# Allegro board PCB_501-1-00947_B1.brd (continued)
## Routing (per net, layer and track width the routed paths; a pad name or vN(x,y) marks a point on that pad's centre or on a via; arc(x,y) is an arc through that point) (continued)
ENET_RST_B: length 119.4
  TOP w0.102: U7.R2 67.89,80.97 68.32,80.54 68.32,80.34 69.49,79.17
  TOP w0.127: v1(57.75,30.35) 63.21,30.35 v1(63.97,31.11) ; v1(70.86,78.77) 70.83,78.77 70.43,79.17 69.49,79.17 ; v1(30.71,34.12) 30.71,34.17 30.83,34.29 U13.43
  BOTTOM w0.127: v1(57.75,30.35) 54.7,27.3 41.88,27.3 40.02,25.44 28.25,25.44 27.39,26.3 27.39,30.4 27.91,30.91 27.91,32.97 26.93,33.95 26.93,34.46 27.84,35.37 28.92,35.37 30.04,34.25 R131.2 30.63,34.12 v1(30.71,34.12) ; v1(63.97,31.11) 72.01,31.11 76.23,35.33 76.23,65.89 74.9,67.22 74.9,74.07 70.86,78.11 v1(70.86,78.77)
ESPI3_MISO: length 79.2
  TOP w0.102: U7.D9 v2(58.34,78.87)
  L3_INT_1 w0.102: 57.59,76.93 57.59,77.6 58.34,78.35 v2(58.34,78.87)
  L3_INT_1 w0.127: v1(53.89,69.6) 54.66,70.37 54.66,73.67 54.9,73.91 54.9,74.24 57.59,76.93
  L6_INT_2 w0.127: v1(16.47,49.58) 17.54,50.65 17.58,50.65 17.76,50.83 45.94,50.83 v1(54.58,59.46)
  BOTTOM w0.137: v1(53.89,69.6) 53.89,60.73 54.58,60.04 v1(54.58,59.46) ; R358.2 13.35,39.8 14.07,40.52 14.07,43.82 13.21,44.68 13.21,46.32 v1(16.47,49.58) 17.33,50.44 U23.12
ESPI3_MOSI: length 78.3
  TOP w0.102: U7.D8 58.87,78.34 v2(58.87,78.34)
  L3_INT_1 w0.102: v2(58.87,78.34) 58.74,78.21 58.74,77.69
  L3_INT_1 w0.127: 58.74,77.69 58.74,77.34 57.19,75.79 57.19,73.4 55.75,71.96 55.75,69.78 v1(54.73,68.76)
  L6_INT_2 w0.127: v1(55.11,59.05) 46.55,50.5 29.03,50.5 28.47,49.94 25.17,49.94 25.17,49.94 24.8,49.94 24.79,49.94 18.11,49.94 v1(17.8,50.24)
  BOTTOM w0.137: R357.2 12.93,38.95 14.42,40.44 14.42,46.86 v1(17.8,50.24) 18.63,51.07 U23.14 ; v1(54.73,68.76) 55.11,68.38 v1(55.11,59.05)
ESPI3_SCLK: length 79.3
  TOP w0.102: U7.E9 v2(58.87,79.4)
  L3_INT_1 w0.102: v2(58.87,79.4) 58.34,79.4 56.75,77.81 56.75,77.08 55.65,75.97
  L3_INT_1 w0.127: v1(53.09,69.85) 53.15,69.85 53.69,70.38 53.69,74.02 55.65,75.97
  L6_INT_2 w0.127: v1(54.07,59.87) 45.45,51.25 21.26,51.25 v1(20.95,51.55)
  BOTTOM w0.137: v1(54.07,59.87) 53.12,60.82 53.12,69.68 53.09,69.7 v1(53.09,69.85) ; R356.2 13.98,37.89 14.93,38.84 14.93,46.75 17.18,49 18.13,49 19.93,50.8 U23.16 20.53,51.92 20.91,51.55 v1(20.95,51.55)
FB_HPOUTL: length 7.5
  TOP w0.254: FB11.2 112.1,38.11 D23.2 114.16,38.15 R367.2 118.24,38.51 J15.2
FB_HPOUTR: length 17
  TOP w0.254: J15.3 121.19,31.1 115.5,36.79 112.2,36.79 D24.2 112.02,36.76 111.98,36.71 FB12.2
FB_VDD_SD: length 16.5
  L3_INT_1 w0.508: v1(94.07,52.2) 94.42,51.85 104.88,51.85 v1(106.47,53.43)
  BOTTOM w0.508: R102.2 95.72,53.23 Q6.3 v1(94.07,52.2) ; FB42.1 v1(106.47,53.43)
FT_RSTOUT_B: length 6.7
  BOTTOM w0.127: U18.5 103.98,121.14 104.3,121.46 105.35,121.46 105.9,120.91 R159.2
FT_RX1: length 1.9
  BOTTOM w0.137: U18.23 111.06,110.63 U17.3
FT_RX2: length 9.9
  BOTTOM w0.137: U19.3 102.6,103.48 100.85,105.23 100.85,109.34 101.29,109.77 101.29,110.87 101.02,111.13 U18.39
FT_TX1: length 1.9
  BOTTOM w0.137: U18.24 111.06,110.13 U17.2
FT_TX2: length 10.7
  BOTTOM w0.137: U18.40 101.21,111.63 101.71,111.13 101.71,109.52 101.32,109.13 101.32,105.32 103.1,103.54 U19.2
FUSE_FSOURCE: length 2.8
  TOP w0.254: v2(65.85,86.54) 65.86,86.54 66.1,86.3 U7.V8
  BOTTOM w0.254: C93.1 66.21,86.18 v2(65.85,86.54)
  BOTTOM w0.406: v1(78.32,81.9) 78.57,82.14 R30.1
GPANAIO: length 8.7
  TOP w0.102: v2(67.89,84.17) 67.89,84.18 U7.V4
  TOP w0.127: v1(74.36,82.5) 74.66,82.2 TP6.1
  L6_INT_2 w0.102: 69.67,83.05 69.51,83.05 68.39,84.17 v2(67.89,84.17)
  L6_INT_2 w0.127: 69.67,83.05 73.81,83.05 v1(74.36,82.5)
GPIO1: length 7.9
  TOP w0.127: U5.11 19.98,88.67 20.95,89.64 20.95,94.11 21.4,94.56 R762.1
GPIO3: length 3.3
  TOP w0.127: R752.1 12.54,89.23 12.88,88.89 12.99,88.78 13.1,88.67 U5.26
GPIO_EPDC_D4: length 6.8
  TOP w0.102: v2(56.22,91.6) U7.N22
  BOTTOM w0.127: v2(56.22,91.6) 55.57,91.6 54.58,92.58 TP10.1 54.15,92.28 53.46,92.28 53.35,92.39 53.35,92.39 52.04,93.7 52.04,94.39 C366.1
GPIO_SD3_CLK: length 4.9
  TOP w0.137: R444.2 64.29,71.37 64.29,72.03 62.53,73.79 62.53,74.15 62.06,74.62 U7.C1
GPIO_SD3_CMD: length 4.8
  TOP w0.137: R445.2 65.99,72.79 63.12,75.66 U7.E1
GPIO_SD3_DATA0: length 6.5
  TOP w0.137: R436.2 63.08,70.02 63.08,70.02 63.02,70.08 63.02,70.08 63.02,71.19 62.78,71.42 62.5,71.42 62.35,71.58 62.35,72.01 62.15,72.21 61.66,72.21 61.49,72.38 61.49,73.59 60.99,74.09 U7.B2
GPIO_SD3_DATA1: length 6.6
  TOP w0.137: 60.46,74.1 60.46,72.81 62.27,71 62.27,70.61 61.83,70.17 61.83,69.71 62.58,68.96 R437.2
GPIO_SD3_DATA2: length 6.3
  TOP w0.102: 64.46,75.98 63.65,76.79 U7.G2
  TOP w0.127: 64.46,75.98 64.74,75.69 65.93,75.69
  TOP w0.137: R439.2 68.39,74.73 67.99,75.14 66.49,75.14 65.93,75.69
GPIO_SD3_DATA3: length 6.5
  TOP w0.137: R438.2 67.64,74.45 66.78,74.45 66.28,73.95 66.05,73.95 65.82,74.17 65.82,74.37 66.18,74.73 66.18,74.89 65.81,75.26 64.61,75.26 U7.F1
GPIO_SD3_DATA4: length 5.9
  TOP w0.137: U7.F2 63.12,76.2 65.86,73.45 66.24,73.45 66.25,73.45 R440.2
GPIO_SD3_DATA5: length 5.7
  TOP w0.137: U7.E2 62.76,76.05 62.76,75.54 62.97,75.33 63.06,75.33 64.9,73.49 64.9,72.96 65.29,72.57 65.6,72.57 R441.2
GPIO_SD3_DATA6: length 6.2
  TOP w0.137: R443.2 64.88,72.02 64.88,72.03 64.87,72.03 64.19,72.71 64.19,72.99 64.34,73.13 64.34,73.33 64.05,73.61 63.85,73.61 63.7,73.46 63.45,73.46 62.83,74.07 62.83,74.37 62.04,75.16 61.52,75.16
GPIO_SD3_DATA7: length 5.5
  TOP w0.137: 61.53,74.1 U7.B1 61.8,73.82 61.8,72.81 62.02,72.59 63.01,72.59 63.67,71.94 63.67,70.72 R442.2
GPIO_SD3_RESET_B: length 5.6
  TOP w0.102: 64.67,76.26 U7.G1
  TOP w0.127: 64.67,76.26 64.86,76.07 66.09,76.07
  TOP w0.137: R446.2 68.41,75.37 68.21,75.57 66.58,75.57 66.09,76.07
GPIO_SD3_STROBE: length 5.7
  TOP w0.127: 65.24,77.37 U7.J1
  TOP w0.137: 65.24,77.37 66.7,75.91 68.1,75.91 68.2,76 R447.2
GWDOG_RST_B: length 43.5
  TOP w0.102: 70.45,78.5 70.06,78.89 69.18,78.89 68.98,78.69 68.42,78.69 67.36,79.75 U7.N1
  TOP w0.127: v1(73.07,75.18) 73.07,76.28 71.37,77.98 70.97,77.98 70.45,78.5 ; v1(100.69,87.67) 100.73,87.63 101.01,87.63 C382.1
  L3_INT_1 w0.127: v1(100.69,87.67) 94.05,87.67 80.75,74.37 76.21,74.37 75.4,75.18 v1(73.07,75.18)
HP_DETEC: length 21.8
  TOP w0.254: v1(110.99,34.01) R366.2 111.99,34 114.3,34 J15.4 ; v1(97.79,43.05) 97.79,41.56 U24.2
  BOTTOM w0.254: v1(97.79,43.05) 98.05,42.8 101.06,42.8 109.85,34.01 v1(110.99,34.01)
HP_L: length 7.4
  TOP w0.254: U24.31 99.13,40.36 105.02,40.36 105.81,39.57 C274.1
HP_R: length 8.5
  TOP w0.254: U24.29 99.06,39.3 100.09,39.3 100.09,39.29 102.67,39.29 105.81,36.15 C275.1
HPOUTL: length 2.7
  TOP w0.254: C274.2 C369.1 110.2,38.15 FB11.1
HPOUTR: length 2.8
  TOP w0.254: FB12.1 110.33,36.67 C370.1 108.83,35.57 C275.2
HSIC_DATA: length 14.3
  TOP w0.137: J4.1 47.61,68.35 47.6,68.34 47.6,71.92 55.08,79.4 U7.A12
HSIC_STROBE: length 15
  TOP w0.137: U7.B12 55.15,79.93 47.3,72.08 43.98,72.08 J3.1
I2C1_SCL: length 203.3
  TOP w0.127: U7.J2 65.26,78.34 65.65,77.95 65.65,77.41 66.72,76.34 v1(67.31,76.34)
  TOP w0.137: R234.1 89.1,125.21 90.18,124.13 95.49,124.13 102.38,117.24 102.38,113.19 101.6,112.41 101.6,92.12 94.56,85.07 93.68,85.07 93.1,84.5 88.11,84.5 85.25,81.64 85.25,71.93 82.74,69.42 82.74,69.42 81.66,68.35 77.96,68.35 71.2,75.1 71.2,75.58 70.07,76.71 68.28,76.71 67.91,76.34 v1(67.31,76.34) ; R231.1 70.66,70.06 v1(70.72,70.01) 72.58,70.01 80.51,62.08 85.62,62.08 R233.2
  L6_INT_2 w0.102: 54.4,95.32 56.25,93.47 56.25,93.17 58.72,90.7 58.72,87.32 58.49,87.09 58.49,86.65 58.69,86.44 58.69,86.15 58.49,85.95 58.49,83.48 58.9,83.07 58.9,82.59 60.45,81.04 61.17,81.04 61.36,81.23 62.91,81.23 63.5,80.64 63.79,80.64 63.97,80.82 65.39,80.82 65.57,80.64 65.97,80.64 66.15,80.82 66.45,80.82 66.85,80.42 66.85,76.8 v1(67.31,76.34)
  L6_INT_2 w0.127: 54.4,95.32 54.36,95.36 52.31,95.36 50.9,96.77 49.37,96.77 48.57,97.57 25.02,97.57 24.72,97.27 23,97.27 21.79,96.05 21.79,94.88 22.66,94.01 22.66,90.29 23.66,89.28 v1(25.06,89.28)
  BOTTOM w0.137: R232.1 22.88,86.22 22.9,86.22 23.16,86.48 23.16,86.5 23.33,86.68 23.33,87.57 25.05,89.28 v1(25.06,89.28) ; v1(70.72,70.01) 70.43,70.3 70.43,73.51 68.13,75.82 67.83,75.82 v1(67.31,76.34)
I2C1_SDA: length 205.7
  TOP w0.127: U7.K1 65.95,78.16 65.95,77.52 66.7,76.77 v1(67.78,76.77)
  TOP w0.137: R235.1 71.18,71.46 v1(71.18,70.57) 72.75,70.57 80.94,62.39 85.62,62.39 R237.2 ; v1(67.78,76.77) 68.04,77.04 70.24,77.04 71.66,75.63 71.66,75.06 78.02,68.69 81.6,68.69 82.62,69.71 82.62,69.71 84.96,72.05 84.96,81.76 88.72,85.52 94.6,85.52 101.16,92.08 101.16,112.97 101.79,113.6 101.79,117 95.6,123.19 R238.2
  L6_INT_2 w0.102: 54.76,95.68 59.23,91.22 59.23,90.02 59.93,89.32 59.93,86.29 59.04,85.39 59.04,84.02 61.14,81.92 61.53,81.92 62.01,81.43 63.71,81.43 63.99,81.16 65.43,81.16 65.63,81.35 66.95,81.35 67.16,81.15 67.16,79.31 67.78,78.7 v1(67.78,76.77)
  L6_INT_2 w0.127: 54.76,95.68 52.41,95.68 50.94,97.16 49.38,97.16 48.63,97.9 32.1,97.9 31.08,98.92 24.18,98.92 21.51,96.26 21.51,94.87 20.97,94.34 20.97,91.62 21.37,91.22 21.37,88.83 22.33,87.87 23.61,87.87 24,88.26 25.42,88.26 26.12,88.96 v1(26.12,89.28)
  BOTTOM w0.137: v1(67.78,76.77) 71.07,73.48 71.07,70.74 71.18,70.64 v1(71.18,70.57) ; R236.1 24.88,87.08 24.88,87.68 26.12,88.92 v1(26.12,89.28)
I2C2_SCL: length 126.3
  TOP w0.102: U7.K2 65.77,78.87 66.33,78.31 66.33,77.75 66.38,77.71 v1(66.38,77.71)
  TOP w0.137: R242.2 v1(116.55,48.39)
  L3_INT_1 w0.102: 68.81,76.85 68.46,77.2 66.89,77.2 v1(66.38,77.71)
  L3_INT_1 w0.127: 68.81,76.85 69.08,76.58 74.26,76.58 74.87,75.97 80.37,75.97 94.87,90.48 101.94,90.48 v1(101.95,90.47) 104.82,90.47 110.32,95.97 122.98,95.97 124.71,94.25 124.71,56.54 v1(116.55,48.39)
  BOTTOM w0.137: R506.2 102.58,89.83 v1(101.95,90.47) ; v1(66.38,77.71) 66.38,76.97 66.75,76.6 R61.1
I2C2_SDA: length 129.9
  TOP w0.102: U7.K3 v2(64.71,78.87)
  TOP w0.137: R247.2 v1(116.55,45.72)
  L3_INT_1 w0.102: 67.08,76.02 66.27,76.83 66.27,77.21 64.71,78.77 v2(64.71,78.87)
  L3_INT_1 w0.127: 67.08,76.02 67.16,75.94 69.05,75.94 69.41,76.3 74.15,76.3 74.75,75.7 80.54,75.7 94.75,89.9 101.13,89.9 v1(101.19,89.96) 104.7,89.96 110.44,95.69 122.01,95.69 124.36,93.34 124.36,56.89 115.97,48.5 115.97,46.3 v1(116.55,45.72)
  BOTTOM w0.102: R62.1 65.99,77.58 v2(64.71,78.87)
  BOTTOM w0.137: v1(101.19,89.96) 101.44,89.7 R504.2
I2C3_SCL: length 107.9
  TOP w0.127: U7.K5 63.65,79.93 v2(63.65,79.93)
  TOP w0.137: v1(19.4,61.21) 19.4,61.24 R723.2
  L6_INT_2 w0.127: v1(19.4,61.21) 21.04,59.56 21.04,56.3 17.73,52.98 15.98,52.98 14.4,52.98 14.36,52.98 11.64,50.26 11.64,47.13 v1(12.29,46.48) 14.34,46.48 14.69,46.12 18.25,46.12 21.41,49.28 29.03,49.28 29.63,49.88 49.74,49.88 v1(57.27,57.4)
  BOTTOM w0.102: 64.41,75.91 64.41,76.4 63.8,77.01 63.8,77.4 64.03,77.63 64.03,77.95 63.27,78.71 63.27,79 63.65,79.38 v2(63.65,79.93)
  BOTTOM w0.127: R63.1 64.41,74.72 64.41,75.91
  BOTTOM w0.137: R63.1 64.69,74.43 64.69,73.4 66,72.08 66,66.14 v1(57.27,57.4) ; R508.2 13.48,41.51 13.48,43.26 12.29,44.44 v1(12.29,46.48) ; v1(19.4,61.21) R726.2
I2C3_SDA: length 110.3
  TOP w0.127: U7.K6 63.12,80.46 v2(63.12,80.46)
  TOP w0.137: v1(20.45,61.47) 20.31,61.47 R724.2
  L6_INT_2 w0.127: v1(55.95,58.17) 47.95,50.16 29.52,50.16 28.91,49.56 21.29,49.56 18.17,46.44 15.31,46.44 14.41,47.34 v1(12.34,47.34) 11.92,47.75 11.92,50.11 14.52,52.7 15.98,52.7 17.84,52.7 21.41,56.27 21.41,60.51 v1(20.45,61.47)
  BOTTOM w0.102: v2(63.12,80.46) 63.12,79.16 62.98,79.01 62.98,78.74 62.74,78.51 62.74,78.2 63.52,77.42 63.52,76.93 64.05,76.41
  BOTTOM w0.127: 64.05,76.41 64.05,74.11 63.4,73.47 R64.1
  BOTTOM w0.137: v1(12.34,47.34) 11.72,46.72 11.72,44.51 12.93,43.3 R509.2 ; R725.2 18.25,60.86 18.38,60.73 19.71,60.73 v1(20.45,61.47) ; 63.4,73.47 65.67,71.19 65.67,66.28 63.28,63.89 63.28,63.89 58.6,59.21 58.59,59.21 57.55,58.17 v1(55.95,58.17)
I2C4_SCL: length 434.2
  TOP w0.102: U7.C12 v2(56.22,79.93)
  TOP w0.137: v1(19.94,56.92) 20,56.98 20.06,56.98 20.87,57.78 R516.2
  L3_INT_1 w0.127: v1(12.67,53.32) 12.67,51.61 13.22,51.06 13.22,46.78 12.74,46.3 12.74,46.3 12.62,46.18 12.62,45.53 10.64,43.56 10.21,43.56 8.35,41.7 8.35,34.67 5.5,31.83 5.5,18.24 7.22,16.52 12.52,16.52 12.86,16.86 14.26,16.86 21.42,24.02 47.09,24.02 49.2,26.13 49.2,66.12 50.01,66.94 50.01,74.46 51.56,76.01 51.56,76.38 53,77.81 53,78.56 53.23,78.79 v2(53.23,78.81) 53.25,78.81 53.36,78.92 55.21,78.92 v2(56.22,79.93)
  L6_INT_2 w0.127: v1(78.24,106.31) 79.1,107.17 81.56,107.17 81.57,107.18 81.94,107.18 81.95,107.17 99.38,107.17 121.52,85.02 121.52,80.63 121.53,80.63 121.53,70.09 120.89,69.45 120.89,49.7 118.41,47.22 118.41,35.2 113.72,30.51 84.98,30.51 82.6,32.89 v1(82.6,35.33) 80.98,33.71 74.13,33.71 63.77,23.35 62.5,23.35 62.5,23.34 25.89,23.34 25.88,23.35 25.62,23.35 22.32,26.64 15.3,26.64 13.98,27.97 5.45,27.97 4.53,28.89 4.53,47.04 6.9,49.4 8.77,49.4 12.67,53.3 v1(12.67,53.32) 12.98,53.63 15.3,53.63 18.64,56.98 19.89,56.98 v1(19.94,56.92)
  BOTTOM w0.137: R595.2 77.43,105.5 v1(78.24,106.31) ; R33.1 50.8,77.02 51.1,76.72 51.52,76.72 53,78.21 53,78.56 53.23,78.79 v2(53.23,78.81) ; R515.2 91.47,35.39 82.72,35.39 82.66,35.33 v1(82.6,35.33)
I2C4_SDA: length 442
  TOP w0.102: U7.D12 v2(56.75,80.46)
  TOP w0.137: R521.2 33.01,58.78 32.48,59.31 21.6,59.31 18.58,56.29 v1(18.58,56.19)
  L3_INT_1 w0.102: v2(56.75,80.46) 56.22,80.46 55.68,79.92 54.29,79.92
  L3_INT_1 w0.127: v1(13.44,52.7) 13.58,52.57 13.58,46.58 13.05,46.05 13.05,45.57 10.76,43.28 10.32,43.28 8.81,41.76 8.81,35.82 8.78,35.8 8.78,34.59 5.78,31.6 5.78,18.35 7.29,16.84 12.45,16.84 20.77,25.16 46.8,25.16 48.81,27.17 48.81,66.23 49.51,66.92 49.51,74.35 51.28,76.12 v1(51.28,77.19) 50.49,77.19 50.26,77.42 50.26,78.28 51.89,79.92 54.29,79.92
  L6_INT_2 w0.127: v1(18.58,56.19) 18.54,56.19 15.71,53.36 14.09,53.36 v1(13.44,52.7) 10.73,49.99 10.73,49.32 9.5,48.09 6.87,48.09 4.81,46.04 4.81,29.09 5.62,28.28 14.06,28.28 15.41,26.92 22.7,26.92 26,23.62 62.38,23.62 73.07,34.31 80.93,34.31 v1(81.49,34.88) 82.39,35.77 82.79,35.77 83.05,35.51 83.05,33.08 85.17,30.95 113.53,30.95 117.96,35.38 117.96,47.4 120.56,50 120.56,85.4 100.05,105.91 91.38,105.91 90.73,106.56 87.41,106.56 87.14,106.29 79.69,106.29 79.29,106.69 v1(79.29,106.72)
  BOTTOM w0.137: R596.2 76.29,105.25 77.83,106.8 79.21,106.8 v1(79.29,106.72) ; R520.2 91.94,34.88 v1(81.49,34.88) ; R34.1 50.7,77.78 v1(51.28,77.19)
INT_LDO: length 7.4
  TOP w0.203: v1(7.97,82.42) 10.38,82.42 13.03,85.07 U5.35
  BOTTOM w0.203: 7.97,81.86 v1(7.97,82.42)
  BOTTOM w0.254: C542.1 7.97,81.86
JT_PWR: length 4.2
  TOP w0.508: v1(106.45,100.9) 106.8,101.24 C572.1 108.55,101.24 109.06,101.75 H2.1
  BOTTOM w0.254: v1(106.45,100.9) 106.8,101.24 R171.1
JTAG_GND1: length 2.8
  TOP w0.254: H2.7 v1(112.87,100.46)
  BOTTOM w0.254: v1(112.87,100.46) 112.9,100.43 R567.1
JTAG_GND2: length 2.8
  TOP w0.254: H2.9 114.01,102.06 v1(114.01,100.33)
  BOTTOM w0.254: R568.1 v1(114.01,100.33)
JTAG_MOD: length 4.9
  TOP w0.127: U7.U1 70.54,80.99 70.92,80.99 R174.2 71.42,79.68 R387.1
JTAG_TCK: length 68.7
  TOP w0.102: U7.U5 67.36,83.64 v2(67.36,83.64)
  TOP w0.137: v1(110.33,104.27) H2.4
  L3_INT_1 w0.127: v2(67.36,83.64) 67.9,83.64 70.84,80.69 78.68,80.69 87.09,89.11 87.09,104.52 89.93,107.36 102.15,107.36 104.67,104.85 106.19,104.85 107.76,103.28 109.34,103.28 v1(110.33,104.27)
JTAG_TDI: length 69.2
  TOP w0.102: U7.U3 68.95,83.11 v2(68.95,83.11)
  TOP w0.137: v1(111.35,104.39) 112.02,104.39 112.87,105.24 H2.8
  L3_INT_1 w0.127: v2(68.95,83.11) 70.07,82 76.86,82 77.78,82.91 78.77,82.91 86.2,90.34 86.2,105.54 88.99,108.33 104.11,108.33 104.21,108.23 104.22,108.23 108.57,103.89 109.44,103.89 109.82,104.27 109.82,104.52 110.08,104.78 110.96,104.78 v1(111.35,104.39)
  BOTTOM w0.137: v1(111.35,104.39) R169.1
JTAG_TDO: length 68.2
  TOP w0.102: v2(67.36,84.7) 67.36,84.71 U7.U6
  TOP w0.137: v1(111.09,108.46) 111.15,108.46 111.6,108.01 H2.6
  L3_INT_1 w0.127: v1(111.09,108.46) 109.73,109.82 89.22,109.82 85.38,105.98 85.38,90.31 78.54,83.47 70.53,83.47 69.45,84.54 68.79,84.54 68.59,84.34 68.25,84.34 67.89,84.7 v2(67.36,84.7)
JTAG_TMS: length 67.5
  TOP w0.102: v2(68.42,83.64) 68.42,83.64 67.89,83.64 U7.U4
  TOP w0.137: H2.2 v1(109.06,104.39)
  L3_INT_1 w0.127: v2(68.42,83.64) 68.95,83.64 69.41,83.19 78.66,83.19 85.82,90.35 85.82,105.66 89.4,109.24 101.69,109.24 102.23,108.71 107.79,108.71 109.06,107.44 v1(109.06,104.39)
  BOTTOM w0.137: v1(109.06,104.39) R170.1
JTAG_TRST_B: length 67.8
  TOP w0.127: U7.U2 69.47,82.58 70.47,81.59 70.54,81.59 v1(70.55,81.6)
  L3_INT_1 w0.127: v1(70.55,81.6) 76.86,81.6 77.89,82.63 78.89,82.63 86.71,90.45 86.71,105.16 89.5,107.95 103.85,107.95 v1(107.85,103.95)
  BOTTOM w0.127: v1(107.85,103.95) 107.85,102.3 108.42,101.73 112.23,101.73 112.49,101.98 R172.1
LCD1_CLK: length 3
  BOTTOM w0.137: R109.1 10.98,32.84 9.58,32.84 9.07,32.33 J14.32
LCD1_DATA0: length 106.6
  TOP w0.102: U7.D21 v2(51.45,85.77)
  L3_INT_1 w0.102: 46.79,87.05 49.66,87.05 50.94,85.77 v2(51.45,85.77)
  L3_INT_1 w0.127: 46.79,87.05 45.57,87.05 42.45,83.93 42.45,77.17 41.15,75.88 41.15,67.55 40.13,66.52 40.13,66.26 40.54,65.85 40.54,65.59 40.35,65.41 40.09,65.41 39.68,65.81 39.42,65.81 39.23,65.63 39.23,65.36 40.03,64.57 40.03,64.31 39.84,64.12 39.58,64.12 38.78,64.91 38.52,64.91 38.33,64.73 38.33,64.46 39.13,63.67 39.13,63.41 38.94,63.22 38.68,63.22 37.88,64.02 37.62,64.02 37.44,63.83 37.44,63.57 38.23,62.77 38.23,62.51 38.04,62.32 37.78,62.32 36.99,63.12 36.72,63.12 36.06,62.45 36.06,53.96 35.17,53.07 35.17,45.49 25.77,36.09 19.77,36.09 13.1,29.42 13.1,27.36 11.9,26.1 11.9,19.91 11.5,19.51 11.5,17.6 11.31,17.4 v1(9.75,17.4)
  BOTTOM w0.137: J14.1 9.17,16.83 v1(9.75,17.4)
LCD1_DATA1: length 105.5
  TOP w0.137: v1(37.18,77.75) 42.85,77.75 49.81,84.71 U7.A22
  L3_INT_1 w0.127: v1(37.18,77.75) 33.13,73.7 33.13,69.44 32.34,68.65 32.08,68.65 31.62,69.1 31.36,69.1 31.17,68.92 31.17,68.65 31.63,68.2 31.63,67.94 31.44,67.75 31.18,67.75 30.73,68.21 30.46,68.21 30.28,68.02 30.28,67.76 30.73,67.3 30.73,67.04 29.28,65.59 29.01,65.59 28.59,66.01 28.33,66.01 28.14,65.82 28.14,65.56 28.56,65.14 28.56,64.87 28.38,64.69 28.12,64.69 27.69,65.11 27.43,65.11 27.25,64.92 27.25,64.66 27.67,64.24 27.67,63.98 26.9,63.21 26.9,57.99 27.42,57.47 27.42,56.87 26.9,56.34 26.9,49.17 23.13,45.4 22.52,45.4 22.26,45.14 22.26,44.45 22.07,44.27 21.81,44.27 21.03,45.06 20.77,45.06 20.58,44.87 20.58,44.61 21.36,43.83 21.36,43.56 21.18,43.38 20.91,43.38 20.13,44.16 19.87,44.16 19.68,43.97 19.68,43.71 20.46,42.93 20.46,42.66 18.85,41.05 17.75,41.05 17.52,40.82 17.26,40.82 16.97,41.11 16.71,41.11 16.52,40.92 16.52,40.66 16.81,40.37 16.81,40.11 16.63,39.92 16.36,39.92 16.07,40.21 15.81,40.21 15.62,40.02 15.62,39.76 15.91,39.47 15.91,39.21 11.87,35.16 11.87,33.42 6.09,27.65 6.09,19.02 v1(6.32,18.8)
  BOTTOM w0.137: J14.2 6.93,17.33 6.32,17.94 v1(6.32,18.8)
LCD1_DATA2: length 105.6
  TOP w0.137: U7.B22 50.39,84.72 49.89,84.22 49.76,84.22 42.35,76.81 36.88,76.81 v1(36.87,76.81)
  L3_INT_1 w0.127: v1(36.87,76.81) 33.57,73.51 33.57,69.25 27.18,62.86 27.18,62.28 27.36,62.1 27.88,62.1 28.06,61.91 28.06,61.65 27.88,61.46 27.36,61.46 27.18,61.28 27.18,61.01 27.36,60.83 27.88,60.83 28.06,60.64 28.06,60.38 27.88,60.19 27.36,60.19 27.18,60.01 27.18,58.11 27.7,57.58 27.7,56.75 27.18,56.22 27.18,48.35 26.92,48.09 26.66,48.09 26.57,48.18 26.3,48.18 26.12,48 26.12,47.73 26.21,47.64 26.21,47.38 26.02,47.19 25.76,47.19 25.67,47.28 25.41,47.28 25.22,47.1 25.22,46.83 25.31,46.74 25.31,46.48 25.12,46.29 24.86,46.29 24.77,46.38 24.51,46.38 24.32,46.2 24.32,45.94 24.41,45.85 24.41,45.58 24.23,45.4 23.96,45.4 23.87,45.49 23.61,45.49 23.42,45.3 23.42,45.04 23.51,44.95 23.51,44.68 22.75,43.92 22.48,43.92 22.43,43.97 22.17,43.97 21.98,43.78 21.98,43.52 22.03,43.47 22.03,43.2 21.85,43.02 21.58,43.02 21.53,43.07 21.27,43.07 21.08,42.89 21.08,42.62 21.14,42.57 21.14,42.31 20.95,42.12 20.69,42.12 20.63,42.17 20.37,42.17 20.18,41.99 20.18,41.73 20.24,41.67 20.24,41.41 20.05,41.22 19.79,41.22 19.74,41.28 19.47,41.28 19.29,41.09 19.29,40.83 19.34,40.77 19.34,40.51 18.6,39.77 18.33,39.77 17.77,40.33 17.5,40.33 17.32,40.15 17.32,39.88 17.88,39.32 17.88,39.05 17.7,38.87 17.44,38.87 16.87,39.43 16.61,39.43 16.42,39.25 16.42,38.99 16.99,38.42 16.99,38.16 16.64,37.81 15.06,37.81 13.94,36.69 13.94,36.43 14.46,35.9 14.46,35.63 14.28,35.45 14.02,35.45 13.49,35.98 13.22,35.98 13.04,35.79 13.04,35.53 13.57,35 13.57,34.74 13.38,34.55 13.12,34.55 12.59,35.08 12.33,35.08 12.15,34.9 12.15,33.31 6.57,27.73 6.57,19.17 6.76,18.98 6.82,18.92 v1(6.82,18.45)
  BOTTOM w0.137: v1(6.82,18.45) 7.45,17.83 J14.3
LCD1_DATA3: length 104.8
  TOP w0.137: v1(38.28,78.86) 38.96,79.53 43.62,79.53 U7.A23
  L3_INT_1 w0.127: v1(38.28,78.86) 37.79,78.36 37.79,77.71 37.31,77.23 37.31,76.62 33.88,73.19 33.88,72.71 34.07,72.52 35.08,72.52 35.26,72.34 35.26,72.08 35.08,71.89 34.07,71.89 33.88,71.7 33.88,71.44 34.07,71.25 35.08,71.25 35.26,71.07 35.26,70.81 35.08,70.62 34.07,70.62 33.88,70.43 33.88,70.17 34.07,69.98 35.08,69.98 35.26,69.8 35.26,69.54 35.08,69.35 34.12,69.35 28.6,63.83 28.6,63.31 28.42,63.13 28.25,63.13 28.06,62.94 28.06,62.68 28.25,62.49 28.42,62.49 28.6,62.31 28.6,59.91 28.42,59.73 27.69,59.73 27.5,59.54 27.5,58.18 27.98,57.7 27.98,56.63 27.5,56.15 27.5,55.86 27.69,55.67 28.36,55.67 28.55,55.49 28.55,55.22 28.36,55.04 27.69,55.04 27.5,54.85 27.5,54.59 27.69,54.4 28.36,54.4 28.55,54.22 28.55,53.95 28.36,53.77 27.69,53.77 27.5,53.58 27.5,53.32 27.69,53.13 28.36,53.13 28.55,52.95 28.55,52.68 28.36,52.5 27.69,52.5 27.5,52.31 27.5,52.05 27.69,51.86 28.36,51.86 28.55,51.68 28.55,51.41 28.36,51.23 27.69,51.23 27.5,51.04 27.5,50.78 27.69,50.59 28.36,50.59 28.55,50.41 28.55,50.14 28.36,49.96 27.69,49.96 27.5,49.77 27.5,48.28 12.43,33.2 12.43,33.19 7.54,28.3 7.54,21.72 7.75,21.51 7.75,19.38 v1(7.3,18.92)
  BOTTOM w0.137: J14.4 7.58,18.33 7.3,18.61 v1(7.3,18.92)
LCD1_DATA4: length 109.5
  TOP w0.102: v2(50.39,85.77) 50.39,85.77 U7.C22
  TOP w0.137: R204.1 v1(1.49,9.91)
  L3_INT_1 w0.102: v2(50.39,85.77) 49.71,86.44 46.79,86.44
  L3_INT_1 w0.127: v1(11.95,19.33) 11.95,19.34 12.29,19.67 12.29,26.01 13.38,27.16 13.38,29.3 19.79,35.71 25.94,35.71 35.59,45.35 35.59,52.82 36.45,53.69 36.45,60.01 40.92,64.49 40.92,66.53 41.53,67.13 41.53,75.84 41.53,75.84 41.53,75.86 42.73,77.05 42.73,83.78 45.4,86.44 46.79,86.44
  L6_INT_2 w0.127: v1(11.95,19.33) 10.4,19.33 1.49,10.41 v1(1.49,9.91)
  BOTTOM w0.137: v1(11.95,19.33) 11.9,19.33 11.41,18.83 J14.5
LCD1_DATA5: length 105.2
  TOP w0.137: U7.B23 49.86,85.23 43.46,78.83 39.39,78.83 v1(38.8,78.24) ; R203.1 v1(1.49,12.57)
  L3_INT_1 w0.127: v1(9.55,19.33) 8.09,20.79 8.09,21.59 7.82,21.87 7.82,28.19 12.71,33.08 12.71,33.09 28.19,48.57 28.19,48.83 28.05,48.97 28.05,49.23 28.24,49.42 28.5,49.42 28.64,49.28 28.9,49.28 29.11,49.49 29.11,55.83 28.93,56.02 28.79,56.02 28.6,56.2 28.6,56.47 28.79,56.65 28.93,56.65 29.11,56.84 29.11,57.12 28.93,57.31 28.45,57.31 28.26,57.49 28.26,57.75 28.45,57.94 28.93,57.94 29.11,58.13 29.11,58.39 28.93,58.58 28.45,58.58 28.26,58.76 28.26,59.02 28.45,59.21 28.93,59.21 29.11,59.4 29.11,62.94 35.54,69.37 35.54,74.4 37.67,76.53 37.67,77.11 v1(38.8,78.24)
  L6_INT_2 w0.127: v1(1.49,12.57) 1.49,13.71 5.17,17.4 5.17,18.41 6.6,19.84 9.04,19.84 v1(9.55,19.33)
  BOTTOM w0.137: J14.6 v1(9.55,19.33)
LCD1_DATA6: length 105.2
  TOP w0.137: R206.1 v1(1.19,14.99) ; v1(39.24,80.16) 39.87,80.8 43.83,80.8 U7.A24
  L3_INT_1 w0.127: v1(9.88,19.8) 8.37,21.32 8.37,21.71 8.12,21.96 8.12,28.07 24.47,44.42 24.73,44.42 24.97,44.19 25.23,44.19 25.41,44.37 25.41,44.64 25.18,44.87 25.18,45.13 25.37,45.32 25.63,45.32 25.86,45.08 26.13,45.08 26.31,45.27 26.31,45.53 26.08,45.76 26.08,46.03 26.71,46.66 26.97,46.66 27.29,46.34 27.56,46.34 27.74,46.52 27.74,46.78 27.42,47.11 27.42,47.37 28.28,48.23 28.54,48.23 29.25,47.52 29.48,47.52 29.67,47.71 29.67,48 28.99,48.68 28.99,48.94 29.73,49.67 29.73,63.16 35.82,69.25 35.82,74.29 39.24,77.71 39.24,80.16 v1(39.24,80.16)
  L6_INT_2 w0.127: v1(1.19,14.99) 1.19,15.42 6.09,20.32 9.34,20.32 9.86,19.8 v1(9.88,19.8)
  BOTTOM w0.137: v1(9.88,19.8) 9.86,19.8 9.83,19.83 J14.7
LCD1_DATA7: length 105
  TOP w0.102: U7.F20 53.04,86.3 v2(53.04,86.3)
  L3_INT_1 w0.102: 48.92,89.83 51.96,89.83 53.93,87.87 53.93,86.68 53.55,86.3 v2(53.04,86.3)
  L3_INT_1 w0.127: 48.92,89.83 42.7,89.83 40.58,87.72 40.58,82.68 39.77,81.86 39.77,80.28 39.76,80.27 39.76,77.83 36.1,74.17 36.1,69.14 30.03,63.07 30.03,46.59 29.24,45.8 28.98,45.8 28.83,45.96 28.54,45.96 28.35,45.77 28.35,45.51 28.53,45.33 28.53,45.08 27.24,43.79 26.87,43.79 26.68,43.98 26.68,44.4 26.5,44.59 26.23,44.59 26.05,44.4 26.05,43.98 25.86,43.79 24.24,43.79 8.4,27.95 8.4,22.07 9.64,20.84 v1(10.26,20.84)
  BOTTOM w0.137: v1(10.26,20.84) 9.75,20.33 J14.8
LCD1_DATA8: length 105.2
  TOP w0.102: U7.E21 v2(51.98,86.3)
  L3_INT_1 w0.102: v2(51.98,86.3) 51.84,86.44 51.84,86.99 50.57,88.25 47.34,88.25
  L3_INT_1 w0.127: v1(10.56,21.34) 10.71,21.19 10.71,19.86 9.32,18.47 9.32,18.04 9.51,17.85 11.1,17.85 11.22,17.98 11.22,19.63 11.51,19.91 11.51,22.98 10.86,23.63 10.86,26.9 12.06,28.09 12.06,29.57 20.42,37.93 25.44,37.93 29.35,41.85 29.35,42.44 33.95,47.03 33.95,53.89 34.78,54.72 34.78,65.03 37.52,67.77 37.52,73.42 41.61,77.52 41.61,85.86 44,88.25 47.34,88.25
  BOTTOM w0.137: J14.10 10.54,21.33 10.55,21.34 v1(10.56,21.34)
LCD1_DATA9: length 105.1
  TOP w0.137: v1(40.2,80.09) 40.21,80.1 43.66,80.1 49.86,86.3 U7.C23
  L3_INT_1 w0.127: v1(40.2,80.09) 40.2,77.84 36.38,74.02 36.38,69.02 36.07,68.71 36.07,68.21 35.87,68.01 35.37,68.01 35.17,67.81 35.17,67.31 34.97,67.11 34.47,67.11 34.27,66.92 34.27,66.42 34.07,66.22 33.57,66.22 33.37,66.02 33.37,65.52 33.17,65.32 32.68,65.32 32.48,65.12 32.48,64.86 32.48,64.62 32.28,64.42 31.78,64.42 31.58,64.22 31.58,63.72 31.38,63.52 30.88,63.52 30.31,62.95 30.31,62.62 30.49,62.44 30.94,62.44 31.12,62.25 31.12,61.99 30.94,61.8 30.49,61.8 30.31,61.61 30.31,61.35 30.49,61.17 30.94,61.17 31.12,60.98 31.12,60.72 30.94,60.53 30.49,60.53 30.31,60.34 30.31,60.08 30.49,59.9 30.94,59.9 31.12,59.71 31.12,59.45 30.94,59.26 30.49,59.26 30.31,59.07 30.31,54.55 31.21,53.65 31.21,52.03 31.03,51.85 30.59,51.85 30.41,51.66 30.41,51.4 30.59,51.21 31.03,51.21 31.21,51.03 31.21,48.96 31.03,48.78 30.52,48.78 30.33,48.59 30.33,48.33 30.52,48.14 31.03,48.14 31.21,47.96 31.21,47.32 27.34,43.45 26.9,43.45 26.71,43.27 26.71,42.28 26.52,42.09 26.26,42.09 26.08,42.28 26.08,43.27 25.89,43.45 25.63,43.45 25.44,43.27 25.44,42.28 25.25,42.09 24.99,42.09 24.81,42.28 24.81,43.27 24.62,43.45 24.3,43.45 23.91,43.06 23.91,42.8 24.29,42.42 24.29,42.15 24.1,41.97 23.84,41.97 23.46,42.35 23.19,42.35 23.01,42.16 23.01,41.9 23.39,41.52 23.39,41.26 23.2,41.07 22.94,41.07 22.56,41.45 22.3,41.45 21.65,40.81 21.65,40.54 22.27,39.93 22.27,39.67 22.08,39.48 21.82,39.48 21.2,40.09 20.94,40.09 8.83,27.99 8.83,22.37 v1(9.37,21.83)
  BOTTOM w0.137: v1(9.37,21.83) J14.11
LCD1_DATA10: length 105.2
  TOP w0.137: U7.B24 49.29,86.3 49.15,86.16 48.66,86.16 43.83,81.33 v1(40.61,81.33) ; R210.1 v1(1.62,17.53)
  L3_INT_1 w0.127: v1(40.61,81.33) 40.65,81.29 40.65,77.81 36.66,73.83 36.66,68.24 31.55,63.13 31.55,59.27 30.69,58.41 30.69,57.3 30.88,57.11 31.65,57.11 31.84,56.93 31.84,56.67 31.65,56.48 30.88,56.48 30.69,56.29 30.69,56.03 30.88,55.84 31.65,55.84 31.84,55.66 31.84,55.4 31.65,55.21 30.88,55.21 30.69,55.02 30.69,54.56 31.52,53.73 31.52,50.36 32.29,49.59 32.29,49.22 32.03,48.96 31.66,48.96 31.4,48.7 31.4,48.33 31.55,48.18 31.55,47.27 27.46,43.17 27.12,43.17 26.99,43.05 26.99,42.16 26.64,41.81 25.4,41.81 23.87,40.28 23.61,40.28 23.33,40.56 23.07,40.56 22.88,40.37 22.88,40.11 23.16,39.83 23.16,39.57 22.45,38.87 20.11,38.87 9.11,27.87 9.11,22.48 9.27,22.33 v1(9.92,22.33)
  L6_INT_2 w0.127: v1(9.92,22.33) 5.89,22.33 1.62,18.05 v1(1.62,17.53)
  BOTTOM w0.137: v1(9.92,22.33) J14.12
LCD1_DATA11: length 107
  TOP w0.102: U7.G20 53.57,86.83 v2(53.57,86.83)
  TOP w0.137: R209.1 v1(1.62,20.07)
  L3_INT_1 w0.102: 48.41,89.33 51.99,89.33 53.57,87.75 v2(53.57,86.83)
  L3_INT_1 w0.127: v1(9.56,22.83) 9.56,27.86 20.25,38.56 24.91,38.56 27.64,41.28 27.64,42.14 33.17,47.68 33.17,64.36 36.94,68.12 36.94,73.71 41.05,77.82 41.05,86.44 43.94,89.33 48.41,89.33
  L6_INT_2 w0.127: v1(1.62,20.07) 1.62,20.71 4.24,23.34 9.04,23.34 9.55,22.83 v1(9.56,22.83)
  BOTTOM w0.137: v1(9.56,22.83) J14.13
LCD1_DATA12: length 105.1
  TOP w0.102: v2(52.51,86.83) 52.51,86.83 53.04,86.83 U7.F21
  TOP w0.137: R211.1 v1(1.62,22.61)
  L3_INT_1 w0.102: 47.9,88.82 52.1,88.82 52.89,88.03 52.89,87.73 52.65,87.49 52.65,86.96 v2(52.51,86.83)
  L3_INT_1 w0.127: v1(10.03,23.33) 10.05,23.35 10.05,27.96 20.31,38.21 25.28,38.21 29.05,41.98 29.05,42.62 33.56,47.13 33.56,54.09 34.32,54.85 34.32,65.11 37.22,68.01 37.22,73.52 41.33,77.63 41.33,86.14 44.01,88.82 47.9,88.82
  L6_INT_2 w0.127: v1(10.03,23.33) 9.52,23.84 4.01,23.84 2.78,22.61 v1(1.62,22.61)
  BOTTOM w0.137: J14.14 v1(10.03,23.33)
LCD1_DATA13: length 107.8
  TOP w0.102: v2(51.45,86.83) 51.45,86.83 51.98,86.83 U7.E22
  TOP w0.137: R213.1 v1(1.62,25.15)
  L3_INT_1 w0.102: 46.79,87.45 50.17,87.45 50.79,86.83 v2(51.45,86.83)
  L3_INT_1 w0.127: v1(11.4,23.82) 11.4,25.97 12.81,27.45 12.81,29.52 19.71,36.42 25.61,36.42 34.71,45.53 34.71,53.25 35.65,54.19 35.65,64.96 36.2,65.5 36.46,65.5 37.31,64.66 37.57,64.66 37.75,64.85 37.75,65.11 36.91,65.95 36.91,66.21 37.1,66.4 37.36,66.4 38.2,65.56 38.47,65.56 38.65,65.74 38.65,66.01 37.84,66.82 37.84,67 38.31,67.48 38.31,67.78 40.24,69.71 40.24,72.42 40.09,72.57 40.09,75.21 42.17,77.29 42.17,84.12 45.49,87.45 46.79,87.45
  L6_INT_2 w0.127: v1(1.62,25.15) 10.59,25.15 11.4,24.34 v1(11.4,23.82)
  BOTTOM w0.137: J14.15 11.39,23.83 v1(11.4,23.82)
LCD1_DATA14: length 105.1
  TOP w0.137: U7.D23 50.4,86.83 50.02,87.21 49.69,87.21 49.48,87 49.18,87 48.94,87.24 47.51,87.24 46.52,86.25 v2(46.52,85.96) ; R212.1 v1(1.62,27.69)
  L3_INT_1 w0.127: v2(46.52,85.96) 45.39,85.96 43.34,83.91 43.34,78.75 44.29,77.81 44.29,72.94 43.76,72.41 43.76,66.25 36.91,59.4 36.91,52.59 35.99,51.66 35.99,45.29 28.65,37.94 28.65,37.62 28.85,37.42 28.85,37.16 28.66,36.97 28.4,36.97 28.2,37.17 27.94,37.17 26.12,35.36 19.83,35.36 13.66,29.19 13.66,26.8 12.79,25.92 v1(12.79,24.33)
  L6_INT_2 w0.127: v1(1.62,27.69) 2.07,27.24 10.39,27.24 12.79,24.84 v1(12.79,24.33)
  BOTTOM w0.137: v1(12.79,24.33) J14.16
LCD1_DATA15: length 105.5
  TOP w0.137: v1(44.37,82.51) 44.47,82.51 47.34,85.38 47.34,86.15 47.89,86.7 48.39,86.7 48.66,86.43 48.94,86.43 49.17,86.66 49.69,86.66 U7.C24
  L3_INT_1 w0.127: v1(44.37,82.51) 44.99,81.89 44.99,79.32 45.78,78.53 45.78,70.66 45.05,69.93 45.05,65.77 38.65,59.37 38.65,56.73 39.91,55.47 39.91,54.11 36.81,51.01 36.81,44.22 35.59,43 35.59,42.98 29.66,37.05 29.66,34.12 28.81,33.27 19.25,33.27 19.25,33.27 18.65,33.27 14.29,28.9 14.29,25.24 14.62,24.91 17.7,24.91 17.9,24.71 17.9,23.05 15.56,20.71 14.27,20.71 13.7,21.28 13.7,21.55 13.36,21.89 v1(13.36,24.82)
  BOTTOM w0.137: v1(13.36,24.82) 8.31,24.82 J14.17
LCD1_DATA16: length 105.7
  TOP w0.137: v1(43.79,83.14) 44.56,83.14 46.96,85.54 46.96,86.23 47.7,86.98 48.65,86.98 48.8,86.83 U7.B25
  L3_INT_1 w0.127: v1(13.33,25.83) 13.98,26.47 13.98,29.02 19.18,34.23 19.46,34.23 19.65,34.04 19.65,33.74 19.83,33.55 20.09,33.55 20.28,33.74 20.28,34.04 20.47,34.23 20.73,34.23 20.92,34.04 20.92,33.74 21.1,33.55 21.36,33.55 21.55,33.74 21.55,34.04 21.74,34.23 22,34.23 22.19,34.04 22.19,33.74 22.37,33.55 22.63,33.55 22.82,33.74 22.82,34.04 23.01,34.23 26.83,34.23 29.11,36.5 29.11,36.93 29.46,37.28 29.46,37.55 29.22,37.79 29.22,38.06 29.4,38.24 29.67,38.24 29.91,38 30.17,38 30.36,38.18 30.36,38.45 30.11,38.69 30.11,38.95 30.3,39.14 30.56,39.14 30.81,38.89 31.07,38.89 31.26,39.08 31.26,39.34 31.01,39.59 31.01,39.85 31.2,40.04 31.46,40.04 31.71,39.79 31.97,39.79 32.16,39.98 32.16,40.24 31.91,40.49 31.91,40.75 32.1,40.94 32.36,40.94 32.6,40.69 32.87,40.69 33.05,40.88 33.05,41.14 32.81,41.38 32.81,41.65 32.99,41.83 33.26,41.83 33.5,41.59 33.77,41.59 34.04,41.86 34.04,42.94 35.29,44.19 35.55,44.19 35.81,43.93 36.08,43.93 36.26,44.12 36.26,44.38 36,44.64 36,44.9 36.4,45.3 36.4,51.44 37.34,52.38 37.34,54.47 37.53,54.65 37.77,54.65 37.96,54.84 37.96,55.1 37.77,55.29 37.53,55.29 37.34,55.47 37.34,57.67 37.53,57.85 38.18,57.85 38.37,58.04 38.37,58.3 38.18,58.49 37.53,58.49 37.34,58.68 37.34,58.93 44.25,65.83 44.25,68.33 44.43,68.51 44.59,68.51 44.77,68.7 44.77,68.96 44.59,69.15 44.43,69.15 44.25,69.33 44.25,69.6 44.43,69.78 44.59,69.78 44.77,69.97 44.77,70.23 44.59,70.42 44.43,70.42 44.25,70.6 44.25,72.18 45.31,73.24 45.31,73.82 45.13,74 44.75,74 44.57,74.19 44.57,74.45 44.75,74.64 45.13,74.64 45.31,74.83 45.31,75.09 45.13,75.27 44.75,75.27 44.57,75.46 44.57,75.72 44.75,75.91 45.13,75.91 45.31,76.1 45.31,76.36 45.13,76.54 44.75,76.54 44.57,76.73 44.57,76.99 44.75,77.18 45.13,77.18 45.31,77.37 45.31,77.82 44.35,78.78 44.35,79.09 44.16,79.27 43.81,79.27 43.62,79.46 43.62,79.72 43.81,79.91 44.16,79.91 44.35,80.09 44.35,80.36 44.16,80.54 43.81,80.54 43.62,80.73 43.62,80.99 43.81,81.18 44.16,81.18 44.35,81.36 44.35,81.63 44.16,81.81 43.81,81.81 43.62,82 43.62,82.26 43.79,82.43 v1(43.79,83.14)
  BOTTOM w0.137: v1(13.33,25.83) J14.19
LCD1_DATA17: length 105.3
  TOP w0.102: v2(53.04,87.36) 53.04,87.36 U7.G21 53.57,87.36
  L3_INT_1 w0.102: 49.8,81.98 51.01,83.18 51.01,83.76 52.66,85.41 52.66,86.44 53.04,86.82 v2(53.04,87.36)
  L3_INT_1 w0.127: 49.8,81.98 47.99,80.16 47.99,68.48 47.34,67.84 47.34,62.9 44.87,60.42 44.87,47.71 39.79,42.63 39.79,39.62 38.6,38.43 38.6,33.52 38.14,33.07 37.46,33.07 36.96,32.57 36.96,32.3 38.12,31.15 38.12,30.88 37.93,30.7 37.67,30.7 36.51,31.85 36.25,31.85 36.07,31.67 36.07,31.46 36.6,30.93 36.6,30.72 36.45,30.57 36.24,30.57 35.71,31.1 35.5,31.1 34.61,30.22 34.61,29.96 35.64,28.93 35.64,28.68 35.45,28.49 35.18,28.49 34.16,29.51 33.9,29.51 33.72,29.32 33.72,29.06 34.34,28.44 34.34,28.18 34.15,27.99 33.89,27.99 33.27,28.61 33,28.61 30.2,25.81 19.14,25.81 18.62,26.33 16.19,26.33 16.04,26.18 16.04,25.97 15.89,25.82 15.68,25.82 15.53,25.97 15.53,26.18 15.39,26.33 v1(14.77,26.33)
  BOTTOM w0.137: v1(14.77,26.33) J14.20
LCD1_DATA18: length 105
  TOP w0.102: v2(50.92,87.36) 50.92,87.36 U7.E23
  L3_INT_1 w0.102: 46.97,87.89 50.39,87.89 v2(50.92,87.36)
  L3_INT_1 w0.127: 46.97,87.89 44.04,87.89 43.84,87.69 43.84,87.43 44.31,86.96 44.31,86.7 44.12,86.51 43.86,86.51 43.39,86.98 43.13,86.98 42.94,86.79 42.94,86.53 43.41,86.06 43.41,85.8 43.22,85.61 42.96,85.61 42.49,86.08 42.23,86.08 41.89,85.74 41.89,77.4 37.83,73.34 37.83,67.53 35.25,64.95 35.25,54.45 34.33,53.53 34.33,45.54 33.96,45.17 33.7,45.17 33.22,45.65 32.96,45.65 32.77,45.46 32.77,45.2 33.25,44.72 33.25,44.46 33.06,44.27 32.8,44.27 32.32,44.75 32.06,44.75 31.87,44.57 31.87,44.3 32.35,43.83 32.35,43.56 32.17,43.38 31.9,43.38 31.42,43.85 31.16,43.85 30.98,43.67 30.98,43.41 31.45,42.93 31.45,42.66 31.27,42.48 31,42.48 30.53,42.96 30.26,42.96 30.08,42.77 30.08,42.51 30.56,42.03 30.56,41.77 29.56,40.77 29.29,40.77 29.11,40.95 28.85,40.95 28.66,40.76 28.66,40.5 28.84,40.32 28.84,40.06 28.66,39.87 28.4,39.87 28.21,40.05 27.95,40.05 27.77,39.86 27.77,39.6 27.95,39.42 27.95,39.16 27.76,38.97 27.5,38.97 27.32,39.15 27.05,39.15 26.87,38.97 26.87,38.7 27.05,38.52 27.05,38.26 26.86,38.07 26.6,38.07 26.42,38.25 26.16,38.25 25.97,38.07 25.97,37.81 26.15,37.62 26.15,37.36 25.62,36.83 23.99,36.83 23.8,37.02 23.8,37.37 23.62,37.56 23.35,37.56 23.17,37.37 23.17,37.02 22.98,36.83 22.72,36.83 22.53,37.02 22.53,37.37 22.35,37.56 22.08,37.56 21.9,37.37 21.9,37.02 21.71,36.83 21.45,36.83 21.26,37.02 21.26,37.37 21.08,37.56 20.81,37.56 20.63,37.37 20.63,37.02 20.44,36.83 19.72,36.83 12.53,29.64 12.53,27.94 v1(11.42,26.83)
  BOTTOM w0.137: v1(11.42,26.83) 11.42,26.83 J14.21
LCD1_DATA19: length 107.5
  TOP w0.137: 50.39,87.36 U7.D24 50.25,87.5 49.72,87.5 49.39,87.83 47.09,87.83 45.56,86.3 45.56,85.64 45.59,85.61 v1(45.59,85.51)
  L3_INT_1 w0.127: v1(17.75,29.21) 19,30.47 20.14,30.47 20.33,30.28 20.33,28.65 20.52,28.46 20.78,28.46 20.96,28.65 20.96,30.28 21.15,30.47 28.54,30.47 28.74,30.67 29.22,30.67 29.54,31 29.8,31 30.82,29.98 31.08,29.98 31.27,30.16 31.27,30.43 30.25,31.44 30.25,31.71 30.44,31.89 30.7,31.89 31.72,30.87 31.98,30.87 32.17,31.06 32.17,31.32 31.15,32.34 31.15,32.61 31.34,32.79 31.6,32.79 32.62,31.77 32.88,31.77 33.07,31.96 33.07,32.22 32.05,33.24 32.05,33.5 32.35,33.81 34.02,33.81 34.32,34.11 34.32,34.73 34.06,34.99 34.06,35.23 38.99,40.16 38.99,43.9 43.54,48.45 43.54,60.45 46.56,63.47 46.56,68.16 47.37,68.97 47.37,80.53 48.06,81.22 48.06,81.62 47.8,81.88 46.5,81.88 46.27,82.1 46.27,84.83 v1(45.59,85.51)
  BOTTOM w0.137: J14.22 15.87,27.33 v1(17.75,29.21)
LCD1_DATA20: length 105.8
  TOP w0.137: v1(45.41,84.65) 45.49,84.73 45.56,84.73 46.04,85.22 46.04,86.26 47.31,87.53 49.15,87.53 U7.C25 49.33,87.36
  L3_INT_1 w0.127: v1(16.6,28.84) 18.73,30.97 27.67,30.97 29.08,32.38 30.12,32.38 31.89,34.15 31.89,34.72 32.41,35.24 33.68,35.24 38.55,40.12 38.55,45.53 38.74,45.72 39.23,45.72 39.42,45.9 39.42,46.17 39.23,46.35 38.74,46.35 38.55,46.54 38.55,46.8 38.74,46.99 39.23,46.99 39.42,47.17 39.42,47.44 39.23,47.62 38.74,47.62 38.55,47.81 38.55,48.62 38.94,49.01 39.2,49.01 40.6,47.61 40.87,47.61 41.05,47.79 41.05,48.06 39.65,49.46 39.65,49.72 39.83,49.91 40.1,49.91 41.5,48.5 41.76,48.5 41.95,48.69 41.95,48.95 40.55,50.36 40.55,50.62 40.73,50.81 41,50.81 42.4,49.4 42.66,49.4 42.85,49.59 42.85,49.85 41.44,51.25 41.44,51.52 42.79,52.86 42.79,60.39 46.17,63.77 46.17,68.35 47.09,69.27 47.09,78.95 45.99,80.04 45.99,84.2 45.54,84.65 v1(45.41,84.65)
  BOTTOM w0.137: v1(16.6,28.84) 15.59,27.83 J14.23
LCD1_DATA21: length 109
  TOP w0.137: U7.E24 50.38,87.89 49.79,88.47 46.61,88.47 44,85.85 v1(44,83.94)
  L3_INT_1 w0.127: v1(14.91,28.61) 14.91,26.92 15.1,26.73 16.89,26.73 17.19,27.03 17.19,27.99 16.86,28.32 16.17,28.32 15.68,28.81 15.68,29.42 19.24,32.99 19.36,32.99 19.37,32.99 28.99,32.99 29.96,33.96 29.96,36.88 37.27,44.18 37.27,51.05 40.73,54.5 40.73,55.88 40.54,56.06 40.13,56.06 39.95,56.25 39.95,56.51 40.13,56.7 40.54,56.7 40.73,56.88 40.73,58.28 40.54,58.47 39.75,58.47 39.57,58.66 39.57,58.92 39.75,59.11 40.54,59.11 40.73,59.29 40.73,59.63 40.93,59.84 40.93,60.1 40.51,60.52 40.51,60.78 40.7,60.97 40.96,60.97 41.38,60.55 41.64,60.55 41.83,60.73 41.83,61 41.41,61.42 41.41,61.68 41.6,61.87 41.86,61.87 42.28,61.45 42.54,61.45 42.73,61.63 42.73,61.89 42.31,62.31 42.31,62.58 42.49,62.76 42.76,62.76 43.18,62.34 43.44,62.34 43.62,62.53 43.62,62.79 43.21,63.21 43.21,63.48 43.39,63.66 43.65,63.66 44.07,63.24 44.34,63.24 44.52,63.43 44.52,63.69 44.1,64.11 44.1,64.37 44.29,64.56 44.55,64.56 44.97,64.14 45.23,64.14 45.43,64.34 45.43,69.8 46.16,70.53 46.16,78.95 45.44,79.68 45.44,82.93 45.17,83.2 44.73,83.2 v1(44,83.94)
  BOTTOM w0.137: J14.24 14.59,28.33 14.81,28.55 14.85,28.55 v1(14.91,28.61)
LCD1_DATA22: length 105.4
  TOP w0.137: U7.D25 49.61,88.13 46.83,88.13 44.77,86.07 44.77,84.13 v1(44.84,84.06)
  L3_INT_1 w0.127: v1(44.84,84.06) 45.71,83.19 45.71,79.86 46.63,78.95 46.63,70.54 45.81,69.72 45.81,64.08 41.03,59.3 41.03,54.25 37.55,50.77 37.55,42.64 36.25,41.34 35.98,41.34 35.62,41.7 35.36,41.7 35.17,41.52 35.17,41.25 35.54,40.89 35.54,40.63 35.35,40.44 35.09,40.44 34.72,40.8 34.46,40.8 34.27,40.62 34.27,40.36 34.64,39.99 34.64,39.73 33.52,38.61 32.11,38.61 30.43,36.94 30.43,35.58 30.92,35.09 30.92,35.08 31.32,34.68 31.32,33.98 30,32.66 28.83,32.66 27.49,31.33 26.63,31.33 26.44,31.51 26.44,32.25 26.26,32.44 25.99,32.44 25.81,32.25 25.81,31.51 25.62,31.33 25.36,31.33 25.17,31.51 25.17,32.25 24.99,32.44 24.72,32.44 24.54,32.25 24.54,31.51 24.35,31.33 24.09,31.33 23.9,31.51 23.9,32.25 23.72,32.44 23.45,32.44 23.27,32.25 23.27,31.51 23.08,31.33 22.82,31.33 22.63,31.51 22.63,32.25 22.45,32.44 22.18,32.44 22,32.25 22,31.51 21.81,31.33 21.55,31.33 21.36,31.51 21.36,32.25 21.18,32.44 20.91,32.44 20.73,32.25 20.73,31.51 20.54,31.33 20.28,31.33 20.09,31.51 20.09,32.25 19.91,32.44 19.64,32.44 19.46,32.25 19.46,31.51 19.27,31.33 18.21,31.33 v1(16.22,29.34)
  BOTTOM w0.137: J14.25 8.33,28.86 14.38,28.86 14.85,29.34 15.33,29.34 15.33,29.34 v1(16.22,29.34)
LCD1_DATA23: length 106.5
  TOP w0.102: U7.G23 v2(51.98,88.42)
  L3_INT_1 w0.102: 49.52,82.09 50.8,83.37 50.8,84.58 52.35,86.13 52.35,86.46 52.12,86.69 52.12,86.98 52.34,87.2 52.34,87.55 51.98,87.9 v2(51.98,88.42)
  L3_INT_1 w0.127: v1(19.27,29.84) 19.27,28.01 19.45,27.83 19.96,27.83 20.15,27.64 20.15,26.85 20.34,26.67 20.6,26.67 20.79,26.85 20.79,27.64 20.97,27.83 21.23,27.83 21.42,27.64 21.42,26.85 21.61,26.67 21.87,26.67 22.06,26.85 22.06,27.64 22.24,27.83 22.5,27.83 22.69,27.64 22.69,26.85 22.88,26.67 23.14,26.67 23.33,26.85 23.33,27.64 23.51,27.83 23.77,27.83 23.96,27.64 23.96,26.85 24.15,26.67 24.41,26.67 24.6,26.85 24.6,27.64 24.78,27.83 25.04,27.83 25.23,27.64 25.23,26.85 25.42,26.67 25.68,26.67 25.87,26.85 25.87,27.64 26.05,27.83 26.31,27.83 26.5,27.64 26.5,26.85 26.69,26.67 26.95,26.67 27.14,26.85 27.14,27.64 27.32,27.83 30.75,27.83 33.59,30.67 34.11,30.67 37.64,34.2 37.64,38.12 39.43,39.91 39.43,43.55 44.15,48.27 44.15,60.46 46.96,63.27 46.96,68.04 47.66,68.74 47.66,80.23 49.52,82.09
  BOTTOM w0.137: J14.26 14.25,29.33 14.76,29.84 v1(19.27,29.84)
LCD1_ENABLE: length 110.8
  TOP w0.127: v1(37.51,80.16) 37.51,80.31 39.97,82.77 39.97,83.52 45.86,89.41 50.47,89.41 50.92,88.95 U7.F25
  L3_INT_1 w0.127: v1(37.51,80.16) 31.25,73.91 31.25,70.81 29.82,69.38 26.09,69.38 25.75,69.04 25.75,50.37 25.29,49.91 24.33,49.91 23.64,50.6 23.64,54.64 23.09,55.19 21.99,55.19 21.81,55 21.81,53.18 21.62,52.99 21.36,52.99 21.17,53.18 21.17,55 20.99,55.19 20.72,55.19 20.54,55 20.54,53.18 20.35,52.99 20.09,52.99 19.9,53.18 19.9,55 19.72,55.19 18.92,55.19 18.48,54.75 18.48,52.68 18.67,52.5 19.82,52.5 20.01,52.31 20.01,52.05 19.82,51.86 18.67,51.86 18.48,51.68 18.48,51.41 18.67,51.23 19.82,51.23 20.01,51.04 20.01,50.78 19.82,50.59 18.67,50.59 18.48,50.41 18.48,49.31 17.03,47.85 15.98,47.85 14.72,46.6 14.72,43.59 9.09,37.95 9.09,35.71 9.06,35.68 9.06,32.37 v1(7.24,30.54)
  BOTTOM w0.127: v1(7.24,30.54) 7.45,30.33 J14.28
LCD1_HSYNC: length 104.8
  TOP w0.137: U7.E25 50.03,88.78 46.32,88.78 40.86,83.31 40.86,82.58 v1(39.08,80.8)
  L3_INT_1 w0.127: v1(39.08,80.8) 38.73,80.44 38.73,80.03 32.77,74.07 32.77,70.15 32.47,69.85 31.35,69.85 30.17,68.68 29.92,68.68 29.73,68.49 29.73,66.54 29.58,66.39 29.32,66.39 29.1,66.61 29.1,68.49 28.91,68.68 28.65,68.68 28.46,68.49 28.46,66.54 28.31,66.39 28.05,66.39 27.83,66.61 27.83,68.49 27.64,68.68 27.27,68.68 26.6,68.01 26.6,67.75 26.79,67.56 27.28,67.56 27.47,67.38 27.47,67.11 27.28,66.93 26.79,66.93 26.6,66.74 26.6,66.48 26.79,66.29 27.28,66.29 27.47,66.11 27.47,65.84 27.28,65.66 26.79,65.66 26.6,65.47 26.6,57.9 27.14,57.35 27.14,56.98 26.6,56.44 26.6,49.37 24.09,46.85 23.46,46.85 23.28,47.04 23.28,47.76 23.09,47.94 22.83,47.94 22.64,47.76 22.64,47.04 22.45,46.85 22.06,46.85 21.62,46.42 21.36,46.42 20.9,46.88 20.64,46.88 20.45,46.7 20.45,46.43 20.91,45.97 20.91,45.71 20.73,45.52 20.46,45.52 20,45.98 19.74,45.98 19.55,45.8 19.55,45.54 20.01,45.08 20.01,44.81 19.83,44.63 19.57,44.63 19.11,45.09 18.84,45.09 18.66,44.9 18.66,44.64 19.12,44.18 19.12,43.91 18.93,43.73 18.67,43.73 18.21,44.19 17.94,44.19 17.76,44 17.76,43.74 18.22,43.28 18.22,43.02 14.85,39.64 14.85,38.85 13.71,37.71 13.45,37.71 12.96,38.2 12.7,38.2 12.51,38.01 12.51,37.75 13,37.26 13,37 12.81,36.81 12.55,36.81 12.06,37.3 11.8,37.3 11.61,37.11 11.61,36.85 12.1,36.36 12.1,36.1 11.55,35.55 11.55,33.74 v1(10.17,32.35)
  BOTTOM w0.137: J14.29 9.07,30.83 10.17,31.92 v1(10.17,32.35)
LCD1_PWM: length 96.5
  TOP w0.127: U7.N2 67.33,80.46 68.04,79.76 v1(68.04,79.68)
  TOP w0.254: R758.1 13.61,51.23 v1(14.11,51.23)
  L3_INT_1 w0.102: 54.65,76.97 54.83,76.97 58.19,80.33 58.45,80.33 59.2,79.57 59.63,79.57 59.79,79.73 60.08,79.73 60.24,79.57 61.73,79.57 61.91,79.76 62.2,79.76 62.38,79.57 62.73,79.57 64.02,80.86 65.34,80.86 66.5,79.71 68.01,79.71 v1(68.04,79.68)
  L3_INT_1 w0.127: 54.65,76.97 54.62,76.97 52.82,75.17 v1(52.82,70.68)
  L6_INT_2 w0.127: v1(52.82,70.68) 52.63,70.48 52.63,69.3 53.16,68.77 53.16,63.45 51.82,62.11 51.82,58.97 44.79,51.94 26.22,51.94 24.72,53.45 20.56,53.45 19.54,52.42 15.86,52.42 14.63,52.42 14.11,51.9 v1(14.11,51.23)
  BOTTOM w0.127: J14.50 8.3,42.17 9.11,42.98 9.11,45.34 11.84,48.06 12.36,48.06 14.17,49.87 14.17,50.94 14.12,50.98 14.12,50.99 14.11,51 v1(14.11,51.23)
LCD1_RESET: length 73.1
  TOP w0.127: U7.C21 50.94,85.24 v2(50.92,85.22)
  L3_INT_1 w0.127: v1(23.64,62.64) 16.22,55.22 v1(15.28,55.22)
  L6_INT_2 w0.127: v1(23.64,62.64) 28.04,67.04 39.63,67.04 44.27,71.68 44.27,76.66 43.91,77.02 43.91,80.26 48.73,85.09 50.79,85.09 v2(50.92,85.22)
  BOTTOM w0.127: J14.49 8.87,40.83 8.91,40.86 9.04,40.86 9.16,40.99 9.16,42.57 9.59,43 9.59,45.37 12,47.78 12.48,47.78 14.61,49.92 14.61,51.37 14.17,51.81 14.17,52.64 13.68,53.12 13.68,53.95 13.94,54.21 13.94,54.29 14.86,55.22 v1(15.28,55.22)
LCD1_TP_REF: length 1.5
  BOTTOM w0.305: C266.2 15.38,53.39 U23.9
LCD1_VSYNC: length 109.1
  TOP w0.137: U7.F24 50.92,88.42 50.22,89.12 46.11,89.12 40.48,83.48 40.48,82.85 38.22,80.59 v1(38.22,80.24)
  L3_INT_1 w0.127: v1(38.22,80.24) 31.65,73.66 31.65,70.67 29.93,68.96 26.85,68.96 26.21,68.32 26.21,50.44 25.34,49.57 23.65,49.57 23.25,49.97 23.25,50.4 22.78,50.87 21.18,50.87 20.8,50.49 20.8,49.72 20.07,49 20.07,48.74 20.95,47.86 20.95,47.59 20.77,47.41 20.5,47.41 19.62,48.29 19.36,48.29 19.17,48.1 19.17,47.84 20.06,46.96 20.06,46.7 19.87,46.51 19.61,46.51 18.73,47.39 18.46,47.39 18.28,47.2 18.28,46.94 19.16,46.06 19.16,45.8 18.97,45.61 18.71,45.61 17.83,46.49 17.56,46.49 17.38,46.31 17.38,46.04 18.26,45.16 18.26,44.9 18.07,44.71 17.81,44.71 16.93,45.59 16.67,45.59 16.48,45.41 16.48,45.14 17.36,44.26 17.36,44 17.18,43.82 16.91,43.82 16.03,44.7 15.77,44.7 15.37,44.3 15.37,43.24 14.73,42.6 14.73,42.34 15.43,41.64 15.43,41.37 15.24,41.19 14.98,41.19 14.28,41.89 14.01,41.89 13.83,41.7 13.83,41.44 14.53,40.74 14.53,40.48 14.34,40.29 14.08,40.29 13.38,40.99 13.12,40.99 12.93,40.81 12.93,40.54 13.63,39.84 13.63,39.58 13.45,39.39 13.18,39.39 12.48,40.09 12.22,40.09 12.03,39.91 12.03,39.64 12.73,38.94 12.73,38.68 12.55,38.49 12.29,38.49 11.58,39.19 11.32,39.19 11.07,38.95 11.07,33.99 9.5,32.42 v1(9.5,32.12)
  BOTTOM w0.137: v1(9.5,32.12) 9.5,31.7 9.13,31.33 J14.30
LCD_I2C_SCL: length 6.2
  BOTTOM w0.137: R508.1 11.88,40.96 11.39,40.47 11.32,40.47 10.53,39.68 10.53,39.61 10.51,39.6 10.51,39.16 10.51,39.16 10.51,37.86 9.98,37.33 J14.42
LCD_I2C_SDA: length 6.8
  BOTTOM w0.137: R509.1 10.75,41.88 10.3,41.43 10.3,40.11 10.14,39.94 10.14,38.95 9.52,38.34 9.52,38.12 9.24,37.83 J14.43
LCD_PWR_EN: length 67.7
  TOP w0.127: U7.G24 51.45,88.95 50.72,89.69 45.75,89.69 39.71,83.65 37.65,83.65 v1(36.8,82.79)
  L6_INT_2 w0.127: v1(23.86,64.78) 22.74,63.66 v1(22.74,55.67)
  BOTTOM w0.127: v1(23.86,64.78) 24.78,64.78 36.3,76.3 36.3,82.29 v1(36.8,82.79) ; Q38.1 24.68,42.59 R734.2 25.7,43.61 25.7,48.43 23.01,51.12 23.01,55.41 v1(22.74,55.67)
LD_WLAN_B: length 1.9
  BOTTOM w0.137: R146.1 124.86,88.14 D6.1
LD_WPAN_B: length 1.9
  BOTTOM w0.137: R147.1 124.74,89.28 D7.1
LD_WWAN_B: length 1.5
  BOTTOM w0.137: D5.2 124.15,87 R145.1
LED_BOOT_COMPL: length 7.2
  TOP w0.102: U7.H23 53.04,89.43 51.54,90.93 50.01,90.93
  TOP w0.127: DA1.3 48.85,90.93 50.01,90.93
LED_BOOT_PROC: length 7.9
  TOP w0.102: U7.H22 53.03,88.42 50.89,90.55 49.63,90.55
  TOP w0.127: DA1.4 48.24,90.55 49.63,90.55
LED_WLAN_B: length 35.9
  BOTTOM w0.127: R146.2 121.45,87.38 108.66,87.38 103.86,92.18 98.11,92.18 96.92,90.99 J8.44
LED_WPAN_B: length 37.5
  BOTTOM w0.127: R147.2 120.68,87.76 108.68,87.76 103.98,92.46 96.87,92.46 96.12,91.71 J8.46
LED_WWAN_B: length 34.6
  BOTTOM w0.127: R145.2 122.11,87.1 108.55,87.1 103.75,91.9 98.9,91.9 97.72,90.72 J8.42
LIN1: length 4.3
  TOP w0.254: C260.1 95.06,44.6 96.79,42.87 U24.4
LIN2: length 5.7
  TOP w0.254: U24.3 97.29,42.83 97.29,42.84 97.29,43.3 C318.1
LVLTXR_OE: length 1.8
  TOP w0.127: R640.1 31.75,56.19 31.36,56.58 U45.6
MIC_N: length 5.7
  TOP w0.254: MK1.2 88.1,46.03 R678.2 R679.1 89.27,42.8 R684.2
MIC_P: length 3.7
  TOP w0.254: MK1.1 91.76,46.1 R182.2 91.84,46.08 C318.2
MICBIAS: length 10.7
  TOP w0.254: U24.1 98.3,41.57 98.3,43.68 C272.1 97.01,44.37 96.8,44.58 96.8,45.66 95.37,47.09 R182.1
MIPI_CSI_CLK_N: length 71.7
  TOP w0.104: v1(42.6,75.47) 42.84,75.23 46,75.23 51.01,80.25 52.92,80.25 53.57,80.9 U7.A15 ; J20.20 2.72,47.21 2.23,47.21 2.23,47.21 2.16,47.21 2.01,47.36 1.55,47.36 0.87,48.04 0.87,52.09 3.83,55.05 v1(3.83,55.44)
  BOTTOM w0.104: v1(42.6,75.47) 42.37,75.23 42.22,75.23 39.68,75.23 39.52,75.07 39.35,75.07 39.14,74.85 39.14,74.69 23.18,58.74 7.51,58.74 7.33,58.56 7.18,58.56 6.96,58.34 6.96,58.19 4.22,55.44 v1(3.83,55.44)
MIPI_CSI_CLK_P: length 71.6
  TOP w0.104: J20.19 2.72,47.49 2.27,47.49 2.12,47.64 1.67,47.64 1.15,48.16 1.15,51.97 4.03,54.85 v1(4.43,54.85) ; U7.B15 53.91,81.34 53.91,80.85 53.9,80.83 53.9,80.83 53.04,79.97 51.13,79.97 46.11,74.96 42.84,74.96 v1(42.6,74.72)
  BOTTOM w0.104: v1(42.6,74.72) 42.36,74.95 42.22,74.96 39.8,74.96 23.3,58.46 7.62,58.46 4.43,55.26 v1(4.43,54.85)
MIPI_CSI_D0_N: length 74.1
  TOP w0.104: v1(43.71,76.59) 43.92,76.38 46.21,76.38 50.76,80.92 52.56,80.92 53.05,81.42 53.05,81.51 U7.A16 ; J20.23 2.71,46.01 1.7,46.01 v1(1.46,45.77)
  BOTTOM w0.104: v1(1.46,45.77) 1.23,46 0.97,46 0.7,46.26 0.7,53.58 7.34,60.22 21.98,60.22 22.11,60.35 22.39,60.35 22.52,60.22 22.79,60.22 38.92,76.35 39.15,76.35 39.27,76.47 39.56,76.47 39.68,76.35 43.47,76.35 v1(43.71,76.59)
MIPI_CSI_D0_P: length 74.1
  TOP w0.104: U7.B16 53.4,81.88 53.4,81.37 52.67,80.64 50.88,80.64 46.33,76.1 43.97,76.1 v1(43.71,75.84) ; J20.22 2.71,46.29 1.68,46.29 v1(1.46,46.5)
  BOTTOM w0.104: v1(1.46,46.5) 1.23,46.28 1.09,46.28 0.98,46.38 0.98,53.47 7.46,59.94 22.9,59.94 39.03,76.07 43.47,76.07 v1(43.71,75.84)
MIPI_CSI_D1_N: length 68.8
  TOP w0.104: U7.A14 54.08,80.46 53.13,79.52 51.24,79.52 45.84,74.12 43.95,74.12 v1(43.75,74.31) ; J20.17 2.7,48.42 2.25,48.42 1.69,48.98 1.69,51.17 3.81,53.29 v1(3.81,53.68)
  BOTTOM w0.104: v1(43.75,74.31) 43.52,74.08 43.51,74.07 40.17,74.07 39.96,73.86 39.8,73.86 39.58,73.65 39.58,73.48 23.83,57.73 23.52,57.73 23.41,57.84 23.11,57.84 23,57.73 8.15,57.73 7.96,57.54 7.8,57.54 7.58,57.33 7.58,57.16 4.14,53.72 4.04,53.72 4,53.68 v1(3.81,53.68)
MIPI_CSI_D1_P: length 68.8
  TOP w0.104: v1(43.77,73.57) 43.77,73.58 44.02,73.84 45.96,73.84 51.36,79.24 53.25,79.24 54.13,80.12 54.28,80.12 54.46,80.3 54.46,80.82 U7.B14 ; J20.16 2.73,48.7 2.37,48.7 1.97,49.1 1.97,51.05 4.01,53.09 v1(4.41,53.09)
  BOTTOM w0.104: v1(4.41,53.09) 4.41,53.59 8.26,57.45 23.94,57.45 40.28,73.79 43.54,73.79 v1(43.77,73.57)
